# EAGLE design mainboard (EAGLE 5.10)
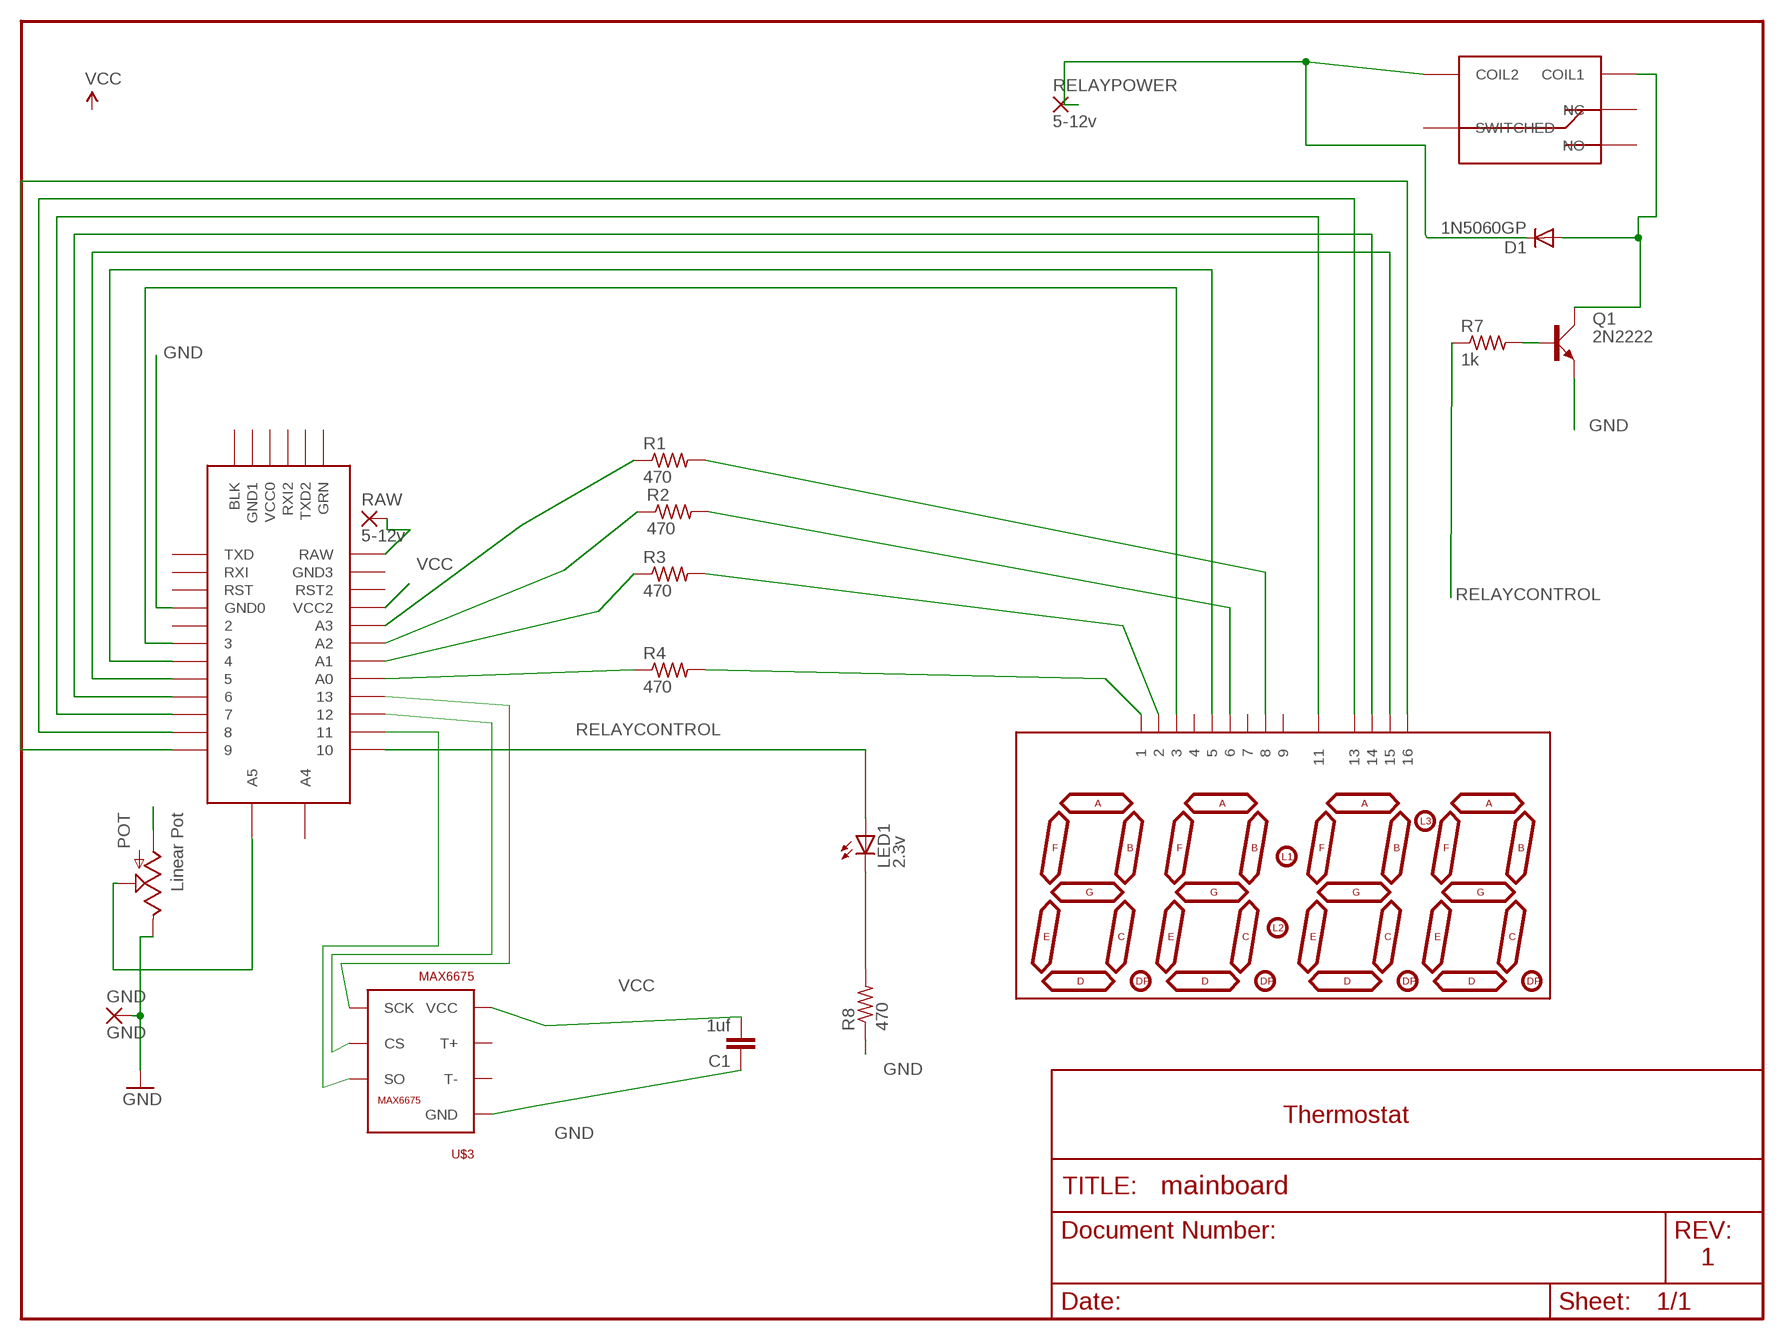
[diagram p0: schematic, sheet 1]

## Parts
C1  1uf  C5/3.5  [C5B3.5]
D1  1N5060GP  [DO15-12]
GND  GND  1,6/0,9  [1,6/0,9]
LED1  2.3v  LED5MM  [LED5MM]
POT  Linear Pot  POT100K_3362U  [3362U]
Q1  2N2222  [TO18A]
R1  470  R-US_0204/7  [0204/7]
R2  470  R-US_0204/7  [0204/7]
R3  470  R-US_0204/7  [0204/7]
R4  470  R-US_0204/7  [0204/7]
R7  1k  R-US_0204/5  [0204/5]
R8  470  R-US_0204/5  [0204/5]
RAW  5-12v  1,6/0,9  [1,6/0,9]
RELAYPOWER  5-12v  1,6/0,9  [1,6/0,9]
U$1  7-SEGMENT-4DIGIT  [7-SEGMENT-4DIGIT-YOUNGSUN]
U$2  ARDUINOPROMINI-DAUGHTER-DOCK  [ARDUINO-PROMINI-DOCK]
U$3  MAX6675  [MAX6675]
U$4  RELAY-COM-00100  [RELAY-COM-00100]

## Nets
COLLECTOR: D1.A Q1.C U$4.COIL1
GND: C1.1 GND.1(P) POT.P$1(E) Q1.E R8.1 U$2.GND(GND0) U$3.GND
N$1: R4.1 U$2.A0
N$2: R3.1 U$2.A1
N$3: R2.1 U$2.A2
N$4: R1.1 U$2.A3
N$5: R4.2 U$1.1
N$6: R3.2 U$1.2
N$7: R2.2 U$1.6
N$8: R1.2 U$1.8
N$9: LED1.K(C) R8.2
N$10: U$2.13 U$3.SCK
N$11: U$2.12 U$3.CS
N$12: U$2.11 U$3.SO
N$13: U$1.3 U$2.3
N$14: U$1.5 U$2.4
N$15: U$1.15 U$2.5
N$16: U$1.14 U$2.6
N$17: U$1.11 U$2.7
N$18: U$1.13 U$2.8
N$19: U$1.16 U$2.9
N$20: Q1.B R7.2
N$21: POT.P$2(S) U$2.A5
N$23: D1.C RELAYPOWER.1(P) U$4.COIL2
RAW: RAW.1(P) U$2.RAW
RELAYCONTROL: LED1.A R7.1 U$2.10
VCC: C1.2 POT.P$3(A) U$2.VCC2 U$3.VCC
Unconnected: U$1.4 U$1.7 U$1.9 U$2.2 U$2.A4 U$2.BLK U$2.GND2(GND1) U$2.GND3 U$2.GRN U$2.RST U$2.RST2 U$2.RXI U$2.RXI2 U$2.TXD U$2.TXD2 U$2.VCC(VCC0) U$3.T+ U$3.T- U$4.NC U$4.NO U$4.SWITCHED

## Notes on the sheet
- Thermostat
- 1

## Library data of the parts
C1 = capacitor-wima:C: CAPACITOR
D1 = diode:1N5060GP: DIODE
GND RAW RELAYPOWER = wirepad:1,6/0,9: THROUGH-HOLE PAD
LED1 = led:LED: LED
POT = SparkFun:POT
Q1 = transistor-small-signal:2N2222: NPN TRANSISTOR
R1-R4 R7 R8 = rcl:R-US_: RESISTOR, American symbol
U$1 = SparkFun:7-SEGMENT-4DIGIT
U$2 = dustinandrews:ARDUINOPROMINI-DAUGHTER-DOCK: Copies the vias from and Arduino Pro Mini onto your board to allow docking as a daughter board.
U$3 = dustinandrews:MAX6675: MAX6675 Cold-Junction-Compensated K-Thermocouple-To-Digital Converter (0C to +1024C); TEMPRANGE: -20C to +85C
U$4 = dustinandrews:RELAY-COM-00100: Relay SPDT Sealed sku: COM-00100 ·5A switching capability ·SPDT configuration ·Power consumption of 200mW ·Standard PCB layout ·Application: Power supply, Air-conditioning, Monitor and Security alarm system, etc?

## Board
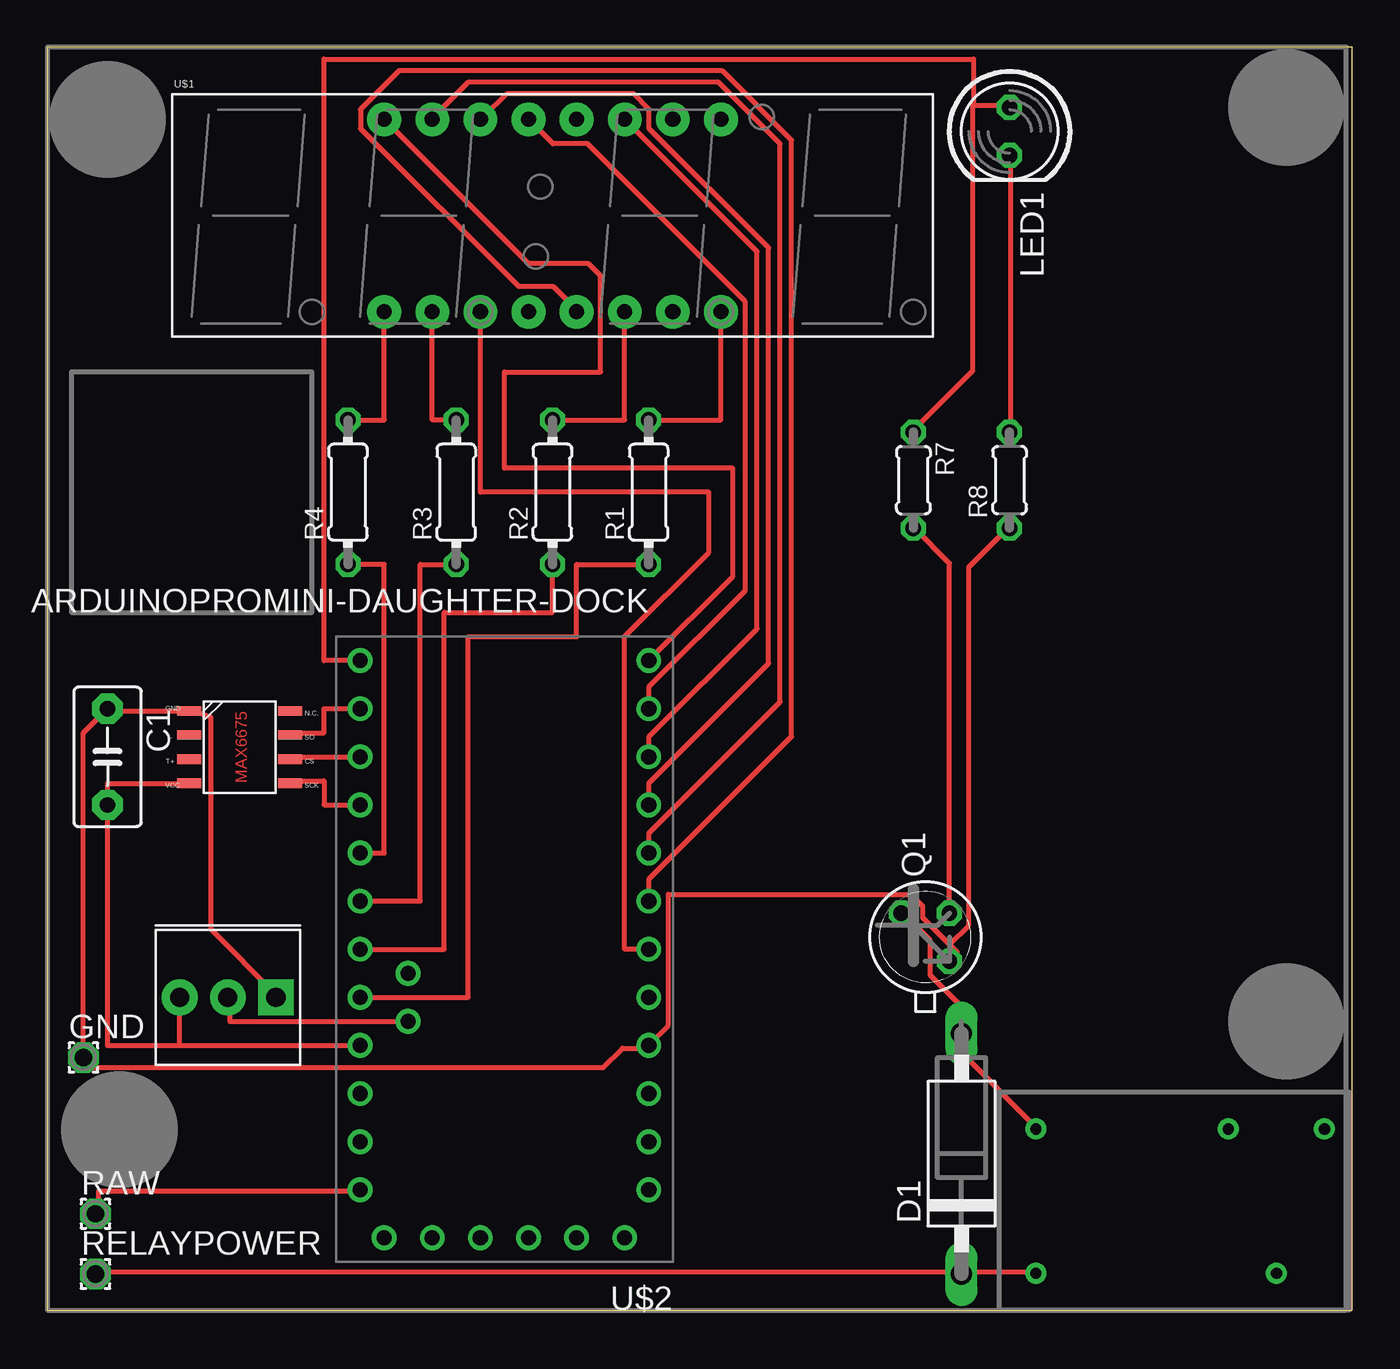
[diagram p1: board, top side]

Size 68.89 x 66.67 mm. Coordinates in mm from the lower left corner, seen from the top.
Outline: 0,0 68.89,0 68.89,66.67 0,66.67 0,0
Copper layers (1*16): Top 0.035mm / dielectric 1.5mm / Bottom 0.035mm
Design rules "default": minimum track width 10mil, minimum drill 24mil, track to track 8mil, track to pad 8mil, pad to pad 8mil, via to via 8mil, smd to smd 8mil, copper to edge 40mil, drill to drill 8mil, minimum pad ring 10mil, minimum via ring 8mil, stop-mask expansion 4mil, vias tented up to drill 0mil, thermal gap 10mil
Holes 0.51 mm at 3.17,62.87 65.41,63.5 65.41,15.24 3.81,9.53

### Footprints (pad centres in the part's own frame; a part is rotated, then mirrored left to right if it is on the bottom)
C5B3.5 = drill 0.813 pad 1.6 octagon: 1 -2.54,0; 2 2.54,0
DO15-12 = drill 1.118 long: A 6.35,0; C -6.35,0
1,6/0,9 = drill 0.914 pad 1.6 octagon: 1 0,0
LED5MM = drill 0.813 octagon: A -1.27,0; K 1.27,0
3362U = drill 1.016 pad 1.88 square: P$1 0,2.54 | drill 1.016 pad 1.88 round: P$2 2.54,2.54; P$3 5.08,2.54
TO18A = drill 0.813 octagon: B 1.27,-1.27; C 1.27,1.27; E -1.27,-1.27
0204/7 = drill 0.813 octagon: 1 -3.81,0; 2 3.81,0
0204/5 = drill 0.813 octagon: 1 -2.54,0; 2 2.54,0
7-SEGMENT-4DIGIT-YOUNGSUN = drill 0.8 pad 1.778 round: 1 -8.89,-5.08; 2 -6.35,-5.08; 3 -3.81,-5.08; 4 -1.27,-5.08; 5 1.27,-5.08; 6 3.81,-5.08; 7 6.35,-5.08; 8 8.89,-5.08; 9 8.89,5.08; 10 6.35,5.08; 11 3.81,5.08; 12 1.27,5.08; 13 -1.27,5.08; 14 -3.81,5.08; 15 -6.35,5.08; 16 -8.89,5.08
ARDUINO-PROMINI-DOCK = drill 0.8 round: 2 1.27,19.05; 3 1.27,16.51; 4 1.27,13.97; 5 1.27,11.43; 6 1.27,8.89; 7 1.27,6.35; 8 1.27,3.81; 9 1.27,1.27; 10 16.51,1.27; 11 16.51,3.81; 12 16.51,6.35; 13 16.51,8.89; A0 16.51,11.43; A1 16.51,13.97; A2 16.51,16.51; A3 16.51,19.05; A4 13.97,17.78; A5 13.97,20.32; BLK 2.54,31.75; GND 1.27,21.59; GND2 5.08,31.75; GND3 16.51,26.67; GRN 15.24,31.75; RAW 16.51,29.21; RST 1.27,24.13; RST2 16.51,24.13; RXI 1.27,26.67; RXI2 10.16,31.75; TXD 1.27,29.21; TXD2 12.7,31.75; VCC 7.62,31.75; VCC2 16.51,21.59
MAX6675 = smd 1.27 x 0.483: CS 4.572,1.778; GND -0.762,4.318; N.C. 4.572,4.318; SCK 4.572,0.508; SO 4.572,3.048; T+ -0.762,1.778; T- -0.762,3.048; VCC -0.762,0.508
RELAY-COM-00100 = drill 0.6 round: COIL1 -3.85,-6.87; COIL2 3.77,-6.87; NC -3.85,3.29; NO -3.85,8.37; SWITCHED 3.77,5.83

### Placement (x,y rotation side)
C1  3.17,29.21 270 top
D1  48.26,8.26 90 top
GND  1.91,13.34 0 top
LED1  50.8,62.23 270 top
POT  12.07,19.05 180 top
Q1  46.36,19.68 90 top
R1  31.75,43.18 90 top
R2  26.67,43.18 90 top
R3  21.59,43.18 90 top
R4  15.88,43.18 90 top
R7  45.72,43.81 270 top
R8  50.8,43.81 90 top
RAW  2.54,5.08 0 top
RELAYPOWER  2.54,1.91 0 top
U$1  26.67,57.78 0 top
U$2  33.02,35.56 180 top
U$3  8.25,27.3 0 top
U$4  59.05,5.71 270 top

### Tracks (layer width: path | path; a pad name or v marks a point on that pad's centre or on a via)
COLLECTOR
  Top 0.254: Q1.C 45.19,20.93 46.61,19.51 46.61,17.68 48.23,16.05 D1.A 48.44,15.85 48.44,13.41 52.1,9.75 U$4.COIL1
GND
  Top 0.254: 48.03,18.9 47.62,18.49 Q1.E 48.03,18.9 | 47.62,19.3 46.2,20.73 46.2,21.34 45.59,21.95 32.79,21.95 32.79,15.04 31.78,14.02 U$2.GND 31.57,13.82 30.35,13.82 29.34,12.8 1.91,12.8 GND.1 1.91,30.48 C1.1 3.17,31.62 U$3.GND 7.59,31.7 8.61,31.32 8.61,20.12 12.07,16.66 POT.P$1 | 47.62,19.3 48.03,18.9 | 47.62,19.3 48.64,20.32 48.64,39.22 50.67,41.25 R8.1
N$1
  Top 0.254: U$2.A0 17.78,24.13 17.78,39.37 R4.1
N$2
  Top 0.254: U$2.A1 19.68,21.59 19.68,39.37 R3.1
N$3
  Top 0.254: U$2.A2 20.95,19.05 20.95,36.83 26.67,36.83 R2.1
N$4
  Top 0.254: U$2.A3 22.22,16.51 22.22,35.56 27.94,35.56 27.94,39.37 R1.1
N$5
  Top 0.254: R4.2 17.78,46.99 U$1.1
N$6
  Top 0.254: R3.2 20.32,46.99 U$1.2
N$7
  Top 0.254: R2.2 30.48,46.99 U$1.6
N$8
  Top 0.254: R1.2 35.56,46.99 U$1.8
N$9
  Top 0.254: R8.2 50.88,46.53 50.88,60.96 LED1.K
N$10
  Top 0.254: U$2.13 14.61,26.67 14.61,27.94 12.83,27.94 U$3.SCK
N$11
  Top 0.254: U$2.12 12.83,29.21 U$3.CS
N$12
  Top 0.254: U$2.11 14.61,31.75 14.61,30.48 12.83,30.48 U$3.SO
N$13
  Top 0.254: U$1.3 22.86,43.18 34.93,43.18 34.93,40.01 30.48,35.56 30.48,19.05 U$2.3
N$14
  Top 0.254: U$2.4 31.78,21.74 31.78,22.76 39.29,30.28 39.29,61.77 35.64,65.43 18.57,65.43 16.54,63.4 16.54,62.38 24.87,54.05 26.7,54.05 27.91,52.83 U$1.5
N$15
  Top 0.254: U$2.5 31.78,24.18 31.78,25.2 38.68,32.11 38.68,61.57 35.43,64.82 22.22,64.82 20.4,62.99 U$1.15
N$16
  Top 0.254: U$2.6 31.78,26.82 31.78,27.84 38.08,34.14 38.08,56.08 31.78,62.38 31.78,63.4 30.96,64.21 24.26,64.21 23.04,62.99 U$1.14
N$17
  Top 0.254: U$2.7 31.78,29.26 31.78,30.28 37.47,35.97 37.47,55.88 U$1.11
N$18
  Top 0.254: U$2.8 31.78,31.9 31.78,32.92 36.86,38 36.86,53.24 28.52,61.57 26.7,61.57 U$1.13
N$19
  Top 0.254: U$2.9 36.2,38.73 36.2,44.45 24.13,44.45 24.13,49.53 29.21,49.53 29.21,54.61 28.57,55.24 25.4,55.24 U$1.16
N$20
  Top 0.254: R7.2 45.8,41.25 47.62,39.42 Q1.B
N$21
  Top 0.254: U$2.A5 9.63,15.24 9.63,16.46 POT.P$2
N$23
  Top 0.254: 48.44,2.03 52.1,2.03 U$4.COIL2 | 48.44,2.03 48.44,3.05 D1.C 48.44,2.03 | 48.44,2.03 2.72,2.03 RELAYPOWER.1
RAW
  Top 0.254: U$2.RAW 16.33,6.3 2.72,6.3 2.72,5.08 RAW.1
RELAYCONTROL
  Top 0.254: U$2.10 14.61,34.29 14.61,66.04 48.9,66.04 48.9,63.6 | 48.9,63.6 50.67,63.6 LED1.A | R7.1 45.8,46.53 48.84,49.58 48.84,63.6 48.9,63.6
VCC
  Top 0.254: U$3.VCC 3.17,27.81 C1.2 3.17,13.97 6.99,13.97 | 6.99,13.97 U$2.VCC2 | 6.99,13.97 POT.P$3

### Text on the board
tDocu: + | - | 0.5 inch | 470 | 1k | 470 | 470 | 470 | 470 | Base | Collector | Emitter(GND) | GND | +5v-12v Raw | +5v Relay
